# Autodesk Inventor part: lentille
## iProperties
Created: 2011-01
Part Number: lentille
Document SubType Name: Modeling
Designer: eric
Density: 1 g/cm^3
Mass: 7.921 g
Surface Area: 30.2156 cm^2
Volume: 7.921 cm^3
Author: eric
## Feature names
1. Base1
